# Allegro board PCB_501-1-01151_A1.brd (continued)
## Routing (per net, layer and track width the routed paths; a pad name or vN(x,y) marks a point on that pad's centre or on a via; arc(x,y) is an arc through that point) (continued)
DRAM_SDQS1_P: length 30.1
  TOP w0.102: v1(83.74,51.44) 83.74,51 83.95,50.8 83.95,48.77 82.3,47.12 82.3,45.1 82.99,44.41 U7.C7 ; v1(76.53,51.82) 76.53,51.56 76.33,51.36 76.33,51.09 76.15,50.91 76.15,50.7 76.04,50.59 75.83,50.59 75.72,50.47 75.72,50.26 75.6,50.15 75.39,50.15 75.28,50.04 75.28,49.83 75.17,49.72 74.96,49.72 74.85,49.61 74.85,49.4 74.74,49.29 74.53,49.29 73.37,48.13 72.6,48.13 72.47,48 72.2,48 72.06,48.13 69.56,48.13 69.45,48.02 69.15,48.02 69.04,48.13 68.77,48.13 68.1,47.46 66.67,47.46 U6.T1
  BOTTOM w0.102: v1(83.74,51.44) 83.95,51.23 83.95,51.03 83.85,50.92 78.57,50.92 78.47,50.83 76.45,50.83 76.33,50.95 76.33,51.61 v1(76.53,51.82)
DRAM_SDWE#: length 34.9
  TOP w0.142: U6.J1 67.4,41.78 67.75,41.43 68.3,41.43 68.69,41.83 70.24,41.83 70.38,41.69 70.38,41.41 70.52,41.27 71.3,41.27 71.44,41.13 71.44,40.79 71.3,40.65 71,40.65 70.91,40.56 70.91,40.25 71,40.16 v1(71.36,40.16) ; v1(79.41,37.61) 80.1,37.61 80.23,37.74 80.23,38.25 80.65,38.66 80.65,39.42 81.36,40.12 81.36,41.66 80.65,42.37 80.65,43.03 81.06,43.44 81.26,43.44 81.59,43.1 81.82,43.1 82.08,43.37 82.08,43.58 81.59,44.08 81.16,44.08 80.28,43.19 80.28,42.17 80.98,41.46 80.98,40.25 80.28,39.55 80.28,38.73 79.81,38.25 U7.L3
  BOTTOM w0.142: v1(71.36,40.16) 71.36,40.52 71.5,40.66 71.7,40.66 71.95,40.41 71.95,39.98 72.06,39.88 73.75,39.88 73.97,39.65 74.37,39.65 74.56,39.85 74.75,39.85 76.59,38.01 77.47,38.01 77.87,37.61 v1(79.41,37.61)
DRAM_VREF: length 41.8
  TOP w0.254: U7.M8 v1(84.21,36.81) ; U7.H1 v1(77.81,40.8) ; U6.P4 v1(64.61,46.2)
  L4_SIG2 w0.508: v1(72.39,46.35) 71.64,45.61 69.96,45.61 69.37,46.2 v1(64.61,46.2)
  BOTTOM w0.142: v1(77.81,40.8) 78.21,41.21 ; 78.21,41.21 78.21,41.77 78.44,42.01 79.79,42.01 79.82,41.97 ; 78.21,41.21 79.05,41.21 79.12,41.27
  BOTTOM w0.381: R66.1 R68.2 67.06,50.06 C88.1 67.08,49.43 66.16,48.51 65.15,48.51 64.75,48.11 C73.1 64.75,46.91 64.61,46.77 v1(64.61,46.2) ; v1(77.81,40.8) 77.36,41.26 C64.1 ; 79.12,41.27 80.14,42.29 80.9,42.29 82.8,40.39 82.8,37.97 83.19,37.59 C63.1 84.31,36.91 v1(84.21,36.81)
  BOTTOM w0.508: v1(72.39,46.35) 72.95,46.92 75.1,46.92 76.14,45.87 76.14,41.84 76.73,41.26 C64.1
DRAM_ZQPAD: length 2.6
  TOP w0.142: U6.N4 v1(64.61,45.4)
  BOTTOM w0.142: 65.75,45 65.24,45 64.84,45.4 v1(64.61,45.4)
  BOTTOM w0.381: 65.75,45 66.35,45 R65.1
ED_EN_A: length 3.5
  BOTTOM w0.142: U10.9 46.22,11.27 R798.1
ED_EN_B: length 3.9
  BOTTOM w0.142: R799.1 46.25,28.82 46.72,28.35 U10.53
EEPR_SCL: length 5.3
  BOTTOM w0.142: R136.2 80.01,61.47 82.17,63.63 83.01,63.63 83.19,63.45 U13.6
EEPR_SDA: length 3.1
  BOTTOM w0.142: U13.5 81.97,62.92 81.15,62.1 R139.2
ENET1_TXD0: length 40.7
  TOP w0.142: U6.E15 v1(54.98,38.17)
  L3_SIG1 w0.142: v1(54.98,38.17) 55.38,38.57 56.75,38.57 56.98,38.34 56.98,33.36 52.95,29.33 52.95,26.14 51.58,24.77 51.58,21.18 50.23,19.83 50.23,14.48 50.67,14.04 50.67,11.94 47.61,8.87 v1(44.56,8.87)
  BOTTOM w0.142: R78.2 v1(44.56,8.87)
ENET1_TXD1: length 46.1
  TOP w0.142: U6.E14 v1(55.78,38.17)
  L3_SIG1 w0.142: v1(42.55,10.03) 43.11,9.47 47.7,9.47 49.4,11.18 49.4,14.88 49.54,15.01 49.54,20.12 49.93,20.51 49.93,21.85 49.5,22.28 49.5,27.46 49.15,27.81 47.71,27.81 47.12,28.41 47.12,32.56 46.83,32.85 46.83,34.16 47.57,34.9 51.25,34.9 51.4,35.06 52.59,35.06 53.23,35.7 53.87,35.7 54.33,36.17 55.15,36.17 55.39,36.41 55.39,37.77 v1(55.78,38.17)
  BOTTOM w0.142: v1(42.55,10.03) 42.8,10.29 R79.2
ENET1_TXEN: length 42.8
  TOP w0.142: U6.F15 v1(54.98,38.97)
  L3_SIG1 w0.142: v1(44.12,10.09) 44.12,15.03 45.1,16.02 46.01,16.02 47.15,17.16 47.15,20.33 46.24,21.24 46.24,22.21 45.76,22.7 45.76,25.07 45.09,25.74 45.09,27.42 44.2,28.3 44.2,31.22 44.89,31.91 44.89,34.09 47.15,36.36 47.15,36.52 47.48,36.85 47.82,36.85 48.35,36.32 48.65,36.32 48.77,36.45 48.77,36.95 48.9,37.07 49.07,37.07 49.2,36.95 49.2,36.45 49.32,36.32 50.55,36.32 52,37.77 53.55,37.77 53.78,38 53.78,38.33 54.02,38.57 54.59,38.57 v1(54.98,38.97)
  BOTTOM w0.142: v1(44.12,10.09) 44.07,10.13 44.07,10.16 43.94,10.29 R80.2
ENET2_TXD0: length 13.7
  TOP w0.142: v1(53.47,33.15) 53.47,33.45 U6.A15
  L3_SIG1 w0.142: v1(53.47,33.15) 52.93,33.69 50.53,33.69 50.18,34.04 48.4,34.04 48.37,34.07 v1(47.91,34.07)
  BOTTOM w0.142: R83.2 44.43,34.16 47.3,34.16 47.4,34.07 v1(47.91,34.07)
ENET2_TXD1: length 16.7
  TOP w0.142: U6.A16 52.96,33.74 52.96,32.85 v1(53.31,32.51)
  L3_SIG1 w0.142: v1(49.43,33.53) 50.2,33.53 50.39,33.34 52.47,33.34 v1(53.31,32.51)
  BOTTOM w0.142: R84.2 42.77,33.64 42.77,34.51 43.12,34.86 46.56,34.86 46.8,34.63 48.33,34.63 v1(49.43,33.53)
ENET2_TXEN: length 12.7
  TOP w0.142: U6.B15 v1(54.98,35.77)
  L3_SIG1 w0.142: v1(54.98,35.77) 53.25,34.03 50.68,34.03 50.17,34.54 47.71,34.54 47.31,34.14 v1(47.31,33.46)
  BOTTOM w0.142: v1(47.31,33.46) 46.86,33.46 46.68,33.29 R85.2
ENET_INT_A: length 3.5
  BOTTOM w0.142: U10.18 41.72,12.25 41.66,12.19 R861.1 R863.2
ENET_INT_B: length 11.1
  TOP w0.142: R862.1 42.46,33.53 42.23,33.76 v1(42.23,34.21)
  BOTTOM w0.142: v1(42.23,34.21) 41.91,33.89 41.91,33.86 41.88,33.83 41.88,32.61 41.77,32.49 R864.2 41.27,30.15 42.22,29.21 U10.44
ENET_REF_CLK: length 35.4
  TOP w0.142: U6.D17 53.23,37.21 v1(52.39,37.21) ; U6.F14 v1(55.78,38.97)
  L3_SIG1 w0.142: v1(51.04,21.59) 51.04,24.94 52.07,25.97 52.07,28.14 51.18,29.02 49.28,29.02 47.91,30.4 v1(47.91,30.85)
  BOTTOM w0.142: v1(55.78,38.97) 55.38,39.37 52.58,39.37 52.18,38.97 R779.2 50.85,38.97 50.37,38.49 ; 50.37,38.49 50.86,37.99 R773.2 51.99,37.99 52.42,38.42 52.69,38.42 52.83,38.27 52.83,37.65 v1(52.39,37.21) ; 50.37,38.49 49.83,38.49 49.44,38.09 49.44,35.61 49.95,35.09 49.95,32.9 v1(47.91,30.85) ; U10.68 51.41,21.95 51.05,21.59 v1(51.04,21.59)
ENETPHY_RESET#: length 46.2
  TOP w0.142: U6.L17 53.17,43.38 53.01,43.22 49.77,43.22 47.46,40.9 47.46,39.82 46.03,38.39 45.62,38.39 45.62,38.38 43.46,38.38 42.55,37.47 41.88,37.47 41.12,38.23 TP48.1 40.39,37.08 v1(40.11,36.81) ; R127.2 48.13,18.92 v1(48.26,19.05)
  L4_SIG2 w0.142: v1(40.11,36.81) 39.62,36.32 39.62,27.67 44.11,23.18 44.11,21.68 46.74,19.05 v1(48.26,19.05)
  BOTTOM w0.142: v1(48.26,19.05) 48.77,19.05 50.17,20.45 U10.71
EXT_EN: length 19.9
  L3_SIG1 w0.142: v1(49.91,12.78) 49.91,14.31 49.89,14.34 49.89,19.98 50.27,20.37 50.27,21.99 49.97,22.3 49.97,25.09 50.67,25.79 50.67,27.5 49.8,28.37 v1(48.41,28.37)
  BOTTOM w0.142: R571.2 50.16,12.57 49.96,12.78 v1(49.91,12.78) ; v1(48.41,28.37) 48.39,28.34 48.22,28.17 U10.56
FB_DCDC6: length 11.7
  TOP w0.142: U1.22 42.67,62.76 42.02,63.41 42.02,69.49 41,70.5 R14.1 R13.1
FT230_CTS#: length 2.8
  BOTTOM w0.142: R174.2 19.48,44.13 U20.6
FT230_RTS#: length 7.7
  TOP w0.142: TP7.1 18.67,51.82 v1(18.67,51.31)
  BOTTOM w0.142: v1(18.67,51.31) 19.06,50.92 19.06,47.21 18.53,46.67 U20.2
GANG_EN: length 2
  TOP w0.142: R154.1 67.49,63.45 U14.34
GATE_PMOS: length 31.1
  TOP w0.142: v1(62.59,8.81) 62.76,8.64 D12.2 ; Q5.1 64.73,7.41 64.63,7.51 R193.2 63.52,7.87 D12.2 ; D12.2 62.76,7.29 62.32,6.86 R192.2 61.36,5.86 61.16,5.66 Q4.1 ; Q6.1 82.6,5.92 82.64,5.97 R262.2 83.29,6.33 83.57,6.6 v1(83.57,6.62)
  L4_SIG2 w0.142: v1(83.57,6.62) 83.11,6.62 82.97,6.48 67.08,6.48 64.38,9.17 62.95,9.17 v1(62.59,8.81)
GPANIO: length 0.6
  TOP w0.142: U6.R13 v1(56.58,47)
GPIO1_IO22: length 2.2
  TOP w0.142: H4.2 14.31,51.75 R841.1
GPIO1_IO24: length 43.9
  TOP w0.142: U6.H17 52.96,40.98 49.28,37.3 49.28,36.81 46.63,34.16 43.89,34.16 43.74,34.31 v1(43.29,34.31)
  L3_SIG1 w0.142: v1(43.29,34.31) 42.22,33.24 42.08,33.24 40.17,31.33 40.17,26.04 40.36,25.85 40.36,25.22 42.51,23.06 42.51,22.51 44.58,20.45 44.58,18.7 41.52,15.64 v1(41.52,9.75)
  BOTTOM w0.142: v1(41.52,9.75) 41.52,10.2 41.66,10.34 R861.2
GPIO1_IO25: length 12.4
  TOP w0.142: R862.2 46.64,33.53 49.77,36.67 49.77,37.24 52.17,39.64 52.17,39.7 53.1,40.63 54.25,40.63 U6.H16
GPIO3_IO03: length 65.6
  TOP w0.142: v1(60.58,36.58) 60.2,36.96 U6.C9 ; H4.20 14.31,38.31 v1(13.97,37.97)
  L3_SIG1 w0.142: v1(60.58,36.58) 60.58,29.34 v1(59.56,28.32)
  L4_SIG2 w0.142: v1(41.91,34.79) 48.85,34.79 50.24,33.4 51.31,33.4 51.59,33.12 51.59,32.19 53.34,30.44 53.34,27.69 53.85,27.18 56.13,27.18 57.28,28.32 v1(59.56,28.32)
  BOTTOM w0.142: v1(41.91,34.79) 38.34,34.79 37.34,33.78 35.43,33.78 33.75,32.1 32.99,32.1 32.51,31.62 28.07,31.62 21.72,37.97 v1(13.97,37.97)
GPIO5_IO02: length 2.6
  TOP w0.142: H4.4 R834.2
GPIO5_IO03: length 2.6
  TOP w0.142: H4.6 R835.2
GPIO5_IO04: length 68
  TOP w0.142: U6.P9 v1(59.78,46.2) ; H4.8 v1(16.13,46.48)
  L3_SIG1 w0.142: v1(59.78,46.2) 59.38,46.6 59.38,47.16 59.15,47.39 59.15,50.64 v1(63.25,54.74)
  L4_SIG2 w0.142: v1(16.13,46.48) 16.93,45.68 25.64,45.68 31.14,51.18 34.42,51.18 35.18,50.42 41.4,50.42 42.31,51.33 48.6,51.33 51.3,54.02 56.62,54.02 59.03,51.61 59.03,49.94 59.82,49.15 59.82,46.68 59.78,46.65 v1(59.78,46.2)
  BOTTOM w0.142: v1(63.25,54.74) 63.14,54.84 R866.2
GPIO5_IO05: length 66.3
  TOP w0.142: H4.10 12.32,45.21 12.08,45.45 R867.2 12.97,47.12 15.75,47.12 16,47.37 v1(16,47.37) ; U6.N8 v1(60.58,45.4)
  L4_SIG2 w0.142: v1(16,47.37) 17.35,46.02 24.43,46.02 25.77,47.36 26.35,47.36 31,52.02 48.32,52.02 51.73,55.43 57.6,55.43 61.68,51.35 61.68,50.08 61.68,50.08 61.68,49.69 61.68,49.68 61.68,48.42 60.99,47.73 60.99,45.8 v1(60.58,45.4)
GPIO5_IO06: length 63.6
  TOP w0.142: v1(10.71,44.17) 10.71,43.67 11.2,43.18 11.94,43.18 12.21,43.45 R868.2 H4.12 ; U6.N11 v1(58.18,45.4)
  L3_SIG1 w0.142: v1(36.68,48.22) 35.88,49.02 28.32,49.02 27.08,47.78 23.42,47.78 23.33,47.88 22.82,47.88 22.31,48.39 19.05,48.39 16.51,45.85 12.43,45.85 11.08,44.5 11.03,44.5 v1(10.71,44.17)
  L4_SIG2 w0.142: v1(36.68,48.22) 37.13,48.22 37.32,48.42 42.19,48.42 43.94,50.16 48.91,50.16 51.45,52.7 54.99,52.7 57.91,49.78 57.91,49.35 58.15,49.35 58.58,48.92 58.58,45.79 v1(58.18,45.4)
GPIO5_IO07: length 58.5
  TOP w0.142: U6.N10 v1(58.98,45.4) ; H4.14 15.87,42.67 16.53,43.32 20.26,43.32 21.01,44.07 23.11,44.07 v1(23.75,44.7) R869.2
  L4_SIG2 w0.142: v1(58.98,45.4) 59.38,45.79 59.38,49.09 58.64,49.84 58.64,51.45 56.41,53.68 51.44,53.68 48.75,50.98 42.73,50.98 41.78,50.04 34.54,50.04 33.79,50.79 31.24,50.79 25.16,44.7 v1(23.75,44.7)
GPIO5_IO08: length 93.1
  TOP w0.142: v1(25.91,46.74) 25.91,45.97 24.6,44.67 24.6,40.1 21.86,37.36 16.16,37.36 16.05,37.47 13.78,37.47 13,38.24 13,38.24 12.85,38.39 12.85,38.39 12.45,38.8 12.45,40.38 13.47,41.4 H4.16 ; R870.2 v1(72.36,56.77) ; U6.N9 v1(59.78,45.4)
  L3_SIG1 w0.142: v1(72.36,56.77) 69.79,54.2 63.26,54.2 59.5,50.43 59.5,47.43 59.65,47.27 59.65,46.89 60.18,46.36 60.18,46.03 60.1,45.95 60.1,45.72 v1(59.78,45.4)
  L4_SIG2 w0.142: v1(59.78,45.4) 60.18,45.79 60.18,49.29 59.72,49.75 59.72,52.73 57.36,55.09 51.87,55.09 48.46,51.67 31.15,51.67 26.21,46.74 v1(25.91,46.74)
GPIO5_IO09: length 78.2
  TOP w0.142: v1(24.77,47.12) 24.77,45.59 24.26,45.09 24.26,40.37 21.94,38.05 16.45,38.05 15.76,38.73 15.76,39.51 15.14,40.13 H4.18 ; U6.R6 v1(62.21,46.2)
  L4_SIG2 w0.142: v1(62.21,46.2) 61.81,46.6 61.81,47.16 62.06,47.41 62.06,51.56 57.49,56.13 53.85,56.13 53.49,55.78 51.59,55.78 48.17,52.36 30.86,52.36 26.39,47.89 25.54,47.89 v1(24.77,47.12)
  BOTTOM w0.142: R871.2 65.28,53.01 64.17,51.89 64.17,50.81 64.95,50.03 64.95,48.97 64.3,48.32 63.77,48.32 63.38,47.93 63.38,46.83 63.15,46.6 62.61,46.6 v1(62.21,46.2)
HUB_CFG_SEL1: length 6.8
  TOP w0.142: R142.2 R146.1 71.25,59.95 71.37,60.06 71.37,63.83 71.49,63.96 U14.42
HUB_CFG_SEL2: length 2.5
  TOP w0.142: v1(68.33,74.55) 68.45,74.42 68.45,73.75 U14.13
  BOTTOM w0.142: R147.1 68.58,74.29 v1(68.33,74.55) R143.2
HUB_LEDA1#: length 7.4
  TOP w0.203: DA1.3 88.98,97.93 88.97,97.92 88.65,97.92 88.01,97.28 88.01,95.63 88.63,95.02 R150.2 90.17,95.99 90.14,96.02 DA1.2
HUB_LEDA2#: length 6.8
  TOP w0.203: DA2.3 69.99,97.93 69.09,97.03 69.09,95.88 69.72,95.25 70.71,95.25 70.73,95.27 R151.2 71.25,95.79 71.22,95.82 DA2.2
HUB_LEDA3#: length 7.1
  TOP w0.203: DA3.2 67.79,96.02 67.82,95.99 R153.2 67.3,95.27 67.19,95.38 66.17,95.38 65.66,95.88 65.66,97.66 65.93,97.93 DA3.3
HUB_LEDA4#: length 7.6
  TOP w0.203: DA4.2 48.74,95.69 48.77,95.66 R157.2 47.1,95.14 46.48,95.76 46.48,97.66 46.75,97.93 DA4.3
HUB_LEDA5#: length 7
  TOP w0.203: DA5.2 36.04,95.89 35.94,95.79 R158.2 34.27,95.27 33.91,95.63 33.91,97.41 34.42,97.92 34.86,97.92 34.88,97.93 DA5.3
HUB_OCS1#: length 5
  TOP w0.142: R155.2 C161.1 64.42,65.29 64.42,65.55 64.67,65.8 64.67,66.46 65.8,67.59 U14.28
HUB_OCS2#: length 3.7
  TOP w0.142: U14.27 65.8,68.09 65.02,67.31 C162.1 R156.2
HUB_OCS3#: length 3.6
  TOP w0.142: U14.22 65.8,70.59 65.37,71.03 64.83,71.03 R159.2 C163.1
HUB_OCS4#: length 3.5
  TOP w0.142: R160.2 C164.1 65.27,71.63 65.8,71.09 U14.21
HUB_OCS5#: length 25.7
  TOP w0.142: v1(66.17,60.32) 67.18,60.32 67.59,60.74 67.59,61.67 67.81,61.88 67.81,62.86 68.09,63.14 R820.1 68.33,63.63 67.99,63.96 U14.35
  L3_SIG1 w0.142: v1(58.89,73.09) 59.67,73.09 59.83,73.25 61.88,73.25 64.52,70.61 64.52,66.8 65.85,65.47 65.85,60.64 v1(66.17,60.32)
  BOTTOM w0.142: U19.2 58.37,73.03 58.44,73.09 v1(58.89,73.09)
HUB_PWR_EN1: length 43.2
  TOP w0.142: v1(85.6,62.48) 85.6,59.18 82.36,55.95 69.4,55.95 65.37,59.97 65.37,62.94 64.77,63.54 64.77,65.41 65.02,65.65 65.02,66.3 65.8,67.09 U14.29
  BOTTOM w0.142: U18.3 92.33,61.16 91.01,62.48 v1(85.6,62.48)
HUB_PWR_EN2: length 50
  TOP w0.142: U14.26 65.84,68.59 65.7,68.45 65.66,68.45 65.28,68.07 61.47,68.07 61.09,67.69 61.09,65.15 62.49,63.75 62.49,61.1 68.68,54.91 83.36,54.91 87.38,58.93 v1(87.38,61.98)
  BOTTOM w0.142: v1(87.38,61.98) 90.25,61.98 91.06,61.16 U18.4
HUB_PWR_EN3: length 46
  TOP w0.142: U14.23 65.73,70.09 65.72,70.1 65.32,70.1 64.9,69.67 64.9,68.83 64.48,68.42 61.32,68.42 60.74,67.83 60.74,65.01 62.15,63.6 62.15,60.95 68.54,54.56 84.03,54.56 v1(87,57.53)
  BOTTOM w0.142: U18.7 87.25,58.24 87,57.98 v1(87,57.53)
HUB_PWR_EN4: length 56.2
  TOP w0.142: v1(87.38,56.39) 87.38,55.63 85.28,53.53 67.98,53.53 61.11,60.4 61.11,63.17 59.6,64.68 59.6,70.63 60.32,71.35 60.32,72.97 60.89,73.53 64.4,73.53 65.02,72.91 65.02,72.37 65.8,71.59 U14.20
  BOTTOM w0.142: v1(87.38,56.39) 87,56.77 86.61,56.77 85.98,57.4 U18.8
HUB_PWR_EN5: length 22.9
  TOP w0.142: v1(65.28,64.01) 65.28,65.43 65.36,65.51 65.36,66.15 65.8,66.59 U14.30
  L4_SIG2 w0.142: v1(58.17,65.02) 58.64,65.5 63.78,65.5 v1(65.28,64.01)
  BOTTOM w0.142: v1(58.17,65.02) 59.15,66.01 59.15,70.18 59.56,70.59 59.56,73.41 58.67,74.29 U19.1
HUB_RESET#: length 202.2
  TOP w0.142: v1(71.52,57.26) 71.84,57.58 71.84,60.28 72.52,60.96 72.52,62.99 72.37,63.14 R144.1 71.88,63.85 71.99,63.96 U14.43 ; U6.N17 53.32,44.98 52.97,45.33 52.06,45.33 51.56,44.83 48.9,44.83 47.24,43.18 47.24,42.42 45.97,41.15 TP60.1 41.02,41.15 37.72,37.85 v1(32.7,37.85)
  L4_SIG2 w0.142: v1(32.7,37.85) 32.27,37.41 32.27,32.01 30.76,30.51 30.76,16.57 34.98,12.35 48.18,12.35 48.97,11.56 48.97,8.53 55.43,2.08 84.88,2.08 96.9,14.1 96.9,21.8 97.12,22.02 97.12,26.37 97.04,26.45 97.04,26.85 97.12,26.93 97.12,34.49 97.32,34.69 97.32,49.36 95.88,50.8 95.88,54.23 94.42,55.7 88.81,55.7 87.61,56.9 84.84,56.9 83.57,55.63 78.87,55.63 77.34,57.15 75.44,57.15 75.23,57.36 72.18,57.36 72.08,57.26 v1(71.52,57.26)
HUB_VDDA18PLL: length 2.7
  TOP w0.254: U14.62 v1(75.9,72.09)
  BOTTOM w0.381: v1(75.9,72.09) 75.86,72.14 C132.1 C134.1
HUB_VDDDIG18: length 2.8
  TOP w0.254: U14.25 65.66,69.09 v1(65.53,68.96)
  BOTTOM w0.381: C135.1 C136.1 v1(65.53,68.96)
I2C2_CURSENSE_SCL: length 130
  TOP w0.142: v1(37,35.64) 35.98,35.64 34.73,36.9 32.58,36.9 31.15,35.46 28.63,35.46 28.35,35.74 28.35,35.76 26.25,37.86 26.25,43.55 30.05,47.35 31.87,47.35 32.42,46.8 33.17,46.8 33.24,46.86 v1(33.69,46.86) 34.01,47.18 34.01,47.89 32.97,48.93 29.91,48.93 27.46,51.37 v1(24.32,51.37) ; U6.F17 53.4,38.99 v1(53.4,38.97)
  L3_SIG1 w0.142: v1(37,35.64) 37.85,34.8 41.19,34.8 41.83,35.43 43.69,35.43 45.22,36.96 45.22,37.45 46.75,38.97 v1(53.4,38.97) ; v1(24.32,51.37) 24,51.69 19.56,51.69 19.53,51.72 19.47,51.72 18.4,52.8 10.2,52.8 8.51,54.48 8.51,72.77 10.8,75.06 15.62,75.06 17.2,76.64 30.66,76.64 31.02,76.28 31.04,76.28 31.32,76 31.32,75.98 31.62,75.67 v1(31.62,73.41)
  BOTTOM w0.142: U22.6 33.58,46.3 33.69,46.41 v1(33.69,46.86) ; v1(31.62,73.41) 33.02,73.41 33.91,72.52 34.35,72.52 34.6,72.26 U23.6 ; v1(24.32,51.37) 25.21,51.37 25.27,51.44 R181.2
I2C2_CURSENSE_SDA: length 139.9
  TOP w0.142: v1(35.98,34.98) 35.66,35.3 35.59,35.3 34.34,36.55 32.74,36.55 31.39,35.2 31.37,35.2 31.29,35.12 28.49,35.12 28.01,35.6 28.01,35.62 25.91,37.72 25.91,43.7 30.02,47.81 31.91,47.81 32.56,47.15 32.96,47.15 33.02,47.21 33.09,47.21 v1(33.41,47.53) 33.41,47.99 32.82,48.58 29.76,48.58 27.5,50.84 24.01,50.84 v1(23.69,51.16) ; U6.G13 v1(56.58,39.77)
  L3_SIG1 w0.142: v1(35.98,34.98) 35.98,35.6 36.58,36.2 37.47,36.2 38.52,35.14 40.1,35.14 40.89,35.94 43.58,35.94 44.87,37.23 44.87,37.59 47.29,40.01 51.15,40.01 51.79,39.37 56.19,39.37 v1(56.58,39.77) ; v1(23.69,51.16) 19.49,51.16 18.2,52.45 10.05,52.45 8.16,54.34 8.16,72.91 10.68,75.43 15.36,75.43 16.91,76.98 31.47,76.98 32.26,76.2 v1(32.26,73.91)
  BOTTOM w0.142: U22.7 33.89,45.65 34.17,45.92 34.17,47.23 33.87,47.53 v1(33.41,47.53) ; R182.2 25.82,49.91 25.47,50.26 24.59,50.26 v1(23.69,51.16) ; U23.7 35.25,72.39 34.74,72.9 34.04,72.9 33.02,73.91 v1(32.26,73.91)
I2C4_HUB_EEPR_SCL: length 207.6
  TOP w0.142: R89.1 40.61,35.94 39.97,35.31 TP59.1 39.76,34.79 39.76,33.48 38.79,32.51 34.91,32.51 34.87,32.48 31.1,32.48 30.94,32.64 v1(30.49,32.64) ; U14.41 70.99,63.96 70.61,63.58 R137.2 70.38,63.14 69.98,62.75 69.98,61.48 69.96,61.45 R145.1 69.34,60.34 69.34,58.04 70.49,56.9 v1(70.61,56.9)
  L4_SIG2 w0.142: v1(70.61,56.9) 70.61,58.05 71.11,58.55 76.58,58.55 79.16,55.97 83.15,55.97 85.22,58.04 87.16,58.04 87.47,57.73 87.47,57.52 88.95,56.04 94.56,56.04 96.27,54.34 96.27,50.91 98.27,48.9 98.27,14.96 85.04,1.73 55.12,1.73 48.49,8.36 48.49,10.44 47.62,11.3 44.56,11.3 44.09,11.78 35.07,11.78 30.42,16.42 30.42,31.18 30.49,31.25 v1(30.49,32.64)
  BOTTOM w0.142: R136.1 79.23,60.05 78.1,58.93 78.1,56.64 77.5,56.04 71.47,56.04 v1(70.61,56.9)
I2C4_HUB_EEPR_SDA: length 210.3
  TOP w0.142: v1(29.64,32.61) 30.11,32.13 31.87,32.13 31.88,32.12 32.28,32.12 32.29,32.13 38.9,32.13 40.11,33.34 40.11,33.75 41.63,35.27 42.11,35.27 42.19,35.18 TP58.1 43.66,35.18 44.04,34.8 R90.1 ; v1(69.5,57.05) 69.5,57.12 68.83,57.79 68.83,60.83 68.96,60.96 68.96,61.96 68.95,61.97 68.95,62.73 69.36,63.14 R138.2 69.47,63.75 69.85,64.13 70.24,64.13 70.49,64.39 U14.40
  L4_SIG2 w0.142: v1(29.64,32.61) 30.07,32.17 30.07,16.01 34.65,11.43 43.94,11.43 44.58,10.8 45.09,10.8 45.33,10.55 45.33,10.55 54.5,1.38 85.18,1.38 98.62,14.82 98.62,49.04 96.61,51.05 96.61,54.48 94.71,56.39 91.15,56.39 89.5,58.03 89.5,58.45 88.8,59.15 85.69,59.15 84.96,58.42 81.77,58.42 81.26,58.93 70.35,58.93 69.4,57.98 69.4,57.22 69.5,57.12 v1(69.5,57.05)
  BOTTOM w0.142: v1(69.5,57.05) 69.57,57.05 70.93,55.69 77.64,55.69 78.45,56.5 78.45,58.62 79.14,59.31 80.41,59.31 R139.1
I2C4_SCL: length 11.1
  TOP w0.142: U6.J17 51.44,41.78 49.15,39.5 49.15,38.61 46.48,35.94 R89.2
I2C4_SDATA: length 12.9
  TOP w0.142: U6.J16 54.22,41.4 51.56,41.4 49.49,39.33 49.49,38 48.9,37.41 48.9,36.92 46.78,34.8 R90.2
I.MX_ONOFF: length 63.8
  TOP w0.142: v1(60.59,46.22) 60.95,46.58 U6.R8 ; SW3.2 97.21,77.39 97.16,77.34 C598.1 96.67,76.85 91.44,71.63 91.44,61.47 89.66,59.69 89.66,56.64 86.2,53.18 75.11,53.18 75.11,53.18 73.63,53.18 v1(73.28,52.83)
  L3_SIG1 w0.142: v1(73.28,52.83) 72.39,53.72 63.31,53.72 60.95,51.36 60.93,51.36 59.84,50.27 59.84,47.46 60.59,46.72 v1(60.59,46.22)
INT_LDO: length 3.2
  TOP w0.142: C34.1 39.24,55.88 40.49,57.13 U1.35
IOVDD_LCD: length 51.7
  TOP w0.254: Q5.3 65.73,7.77 65.27,8.23 64.18,8.23 v1(63.75,8.66)
  TOP w0.381: C183.1 66.53,4.97 v1(67.72,3.78) 67.72,3.21 68.38,2.55 74.43,2.55 78.49,6.6 79.7,6.6 80.59,7.49 80.59,9.78 81.41,10.6 v1(81.41,11.18) ; C183.1 65.91,5.58 66.28,5.95 R191.2 ; C183.1 C187.1
  L4_SIG2 w0.381: v1(57.99,3.55) 59,2.54 66.47,2.54 v1(67.72,3.78) 67.72,4.7 v1(63.75,8.66)
  BOTTOM w0.254: J9.33 57.5,4.3 57.99,3.81 v1(57.99,3.55)
  BOTTOM w0.381: R195.1 v1(81.41,11.18) 81.41,11.75 81.79,12.13 81.79,12.85 81,13.64 R807.1
IOVDD_LCD_SW_IN: length 8
  TOP w0.142: Q5.2 65.08,6.41 65.02,6.35
  TOP w0.381: R193.1 64.24,6.35 65.86,6.35 66.26,6.75 R191.1 C186.1 FB6.2 FB8.2
JTAG_DACK: length 3.3
  TOP w0.142: H5.19 R848.2
JTAG_DE: length 3.3
  TOP w0.142: R265.1 H5.17
JTAG_MOD: length 27.1
  TOP w0.142: U6.P15 v1(54.98,46.2)
  L3_SIG1 w0.142: v1(35.1,39.66) 35.42,39.98 35.91,39.98 40.64,44.7 40.64,45.85 41.78,46.99 48.01,46.99 48.6,47.58 51.99,47.58 53.37,46.2 v1(54.98,46.2)
  BOTTOM w0.142: R387.1 R569.2 34.99,39.37 35.1,39.48 v1(35.1,39.66)
JTAG_PWR: length 3.8
  TOP w0.381: R264.2 4.3,49.02 C572.1 4.32,49.65 4.26,49.71 H5.2
JTAG_RTCK: length 3.3
  TOP w0.142: R851.2 H5.11
JTAG_SRST#: length 23.8
  TOP w0.142: R856.2 v1(14.22,54.23) ; H5.15 R266.1 12.05,68.97 12.33,68.69 D26.1 12.33,67.99 12.72,67.59 13.56,67.59 15.49,65.66 15.49,58.02 v1(16.52,56.99)
  L3_SIG1 w0.142: v1(14.22,54.23) 14.22,54.68 14.71,55.16 14.72,55.16 15.28,55.72 16.22,55.72 16.51,56.01 16.51,56.52 16.52,56.53 v1(16.52,56.99)
JTAG_TCK: length 66.7
  TOP w0.142: v1(16.3,54.36) 16.3,55.08 15.43,55.94 15.43,56.05 14.64,56.85 14.64,59.53 13.84,60.32 12.32,60.32 12.05,60.6 R852.2 H5.9 ; U6.M14 v1(55.78,44.6)
  L3_SIG1 w0.142: v1(16.3,54.36) 17.53,54.36 17.76,54.59 24.4,54.59 26.49,52.51 36.63,52.51 37.52,51.62 47.93,51.62 49.99,53.68 56.05,53.68 56.77,52.96 56.77,51.31 54.74,49.28 54.74,47.01 55.38,46.36 55.38,45 v1(55.78,44.6)
JTAG_TDI: length 58.1
  TOP w0.142: H5.5 R854.1 12.05,56.08 12.25,55.88 13.46,55.88 v1(13.9,55.44) ; v1(51.81,48.89) 52.36,48.33 52.36,46.73 53.65,45.43 53.91,45.43 54.36,44.98 U6.N16
  L3_SIG1 w0.142: v1(51.81,48.89) 52.26,49.34 52.26,52.53 51.79,53 50.22,53 48.4,51.19 47.04,51.19 46.33,51.19 46.33,51.19 37.34,51.19 37.09,51.44 36.45,52.08 25.14,52.08 24,53.21 21.84,53.21 20.96,54.1 17.91,54.1 17.53,53.72 13.84,53.72 13.46,54.1 13.46,55 v1(13.9,55.44)
JTAG_TDO: length 71.7
  TOP w0.142: H5.13 13.34,66.93 15.11,65.15 15.11,57.02 v1(15.88,56.26) ; U6.N15 54.98,45.4 54.49,45.4 54.25,45.64 54.25,45.83 53.84,46.23 53.63,46.23 52.7,47.16 52.7,48.76 52,49.46 51.9,49.46 v1(51.76,49.6)
  L3_SIG1 w0.142: v1(51.76,49.6) 51.76,50.05 51.92,50.21 51.92,52.38 51.64,52.66 50.36,52.66 48.55,50.85 47.18,50.85 47.18,50.85 46.19,50.85 37.2,50.85 36.74,51.3 36.31,51.73 24.87,51.73 23.9,52.7 19.94,52.7 19.43,53.21 13.84,53.21 12.83,54.23 12.83,55.37 13.72,56.26 v1(15.88,56.26)
JTAG_TMS: length 65
  TOP w0.142: v1(15.64,54.31) 15.64,55.13 15,55.77 15,55.88 14.21,56.67 14.21,59.36 13.74,59.82 12.33,59.82 12.05,59.54 R267.1 H5.7 ; U6.P14 v1(55.78,46.2)
  L3_SIG1 w0.142: v1(55.78,46.2) 55.78,46.34 55.01,47.12 55.01,48.9 55.16,49.06 55.16,49.1 57.2,51.13 57.2,53.14 56.23,54.1 49.66,54.1 47.6,52.04 37.96,52.04 37.05,52.96 27.07,52.96 25.01,55.02 15.89,55.02 15.64,54.77 v1(15.64,54.31)
JTAG_TRST#: length 65.6
  TOP w0.142: R856.1 H5.3 ; R856.1 R855.1 ; R856.1 12.05,54.72 12.32,54.99 13.67,54.99 13.92,54.74 14.47,54.74 v1(14.98,54.23) ; U6.N14 v1(55.78,45.4)
  L3_SIG1 w0.142: v1(55.78,45.4) 56.19,45.8 56.19,49.63 58.26,51.71 58.26,53.85 56.87,55.24 55.5,55.24 54.86,54.61 49.66,54.61 47.44,52.39 38.1,52.39 37.19,53.3 27.21,53.3 25.15,55.37 15.67,55.37 14.98,54.68 v1(14.98,54.23)
JTAG_VREF: length 3.3
  TOP w0.381: R857.1 H5.1
LCD_CS#: length 2.3
  BOTTOM w0.142: J9.31 58.5,6.54 R194.1
LCD_DATA0: length 55.8
  TOP w0.142: v1(69.47,18.29) 69.47,17.26 68.84,16.63 68.1,16.63 66.17,14.69 66.17,9.67 v1(66.78,9.06) ; v1(59.56,22.58) 59.56,22.59 59.56,23.03 58.33,24.26 58.33,29.88 60.55,32.1 60.55,35.83 U6.B9
  L3_SIG1 w0.142: v1(66.78,9.06) 65.91,8.18 62.14,8.18 v1(61.6,8.73)
  BOTTOM w0.142: R236.2 v1(61.6,8.73) 60.5,7.64 J9.27 ; v1(69.47,18.29) 69.47,20.57 69.85,20.96 69.85,22.76 69.47,23.14 SW6.1 68.57,24 68.43,23.86 68.43,22.85 66.12,20.55 64.11,20.55 63.43,21.23 63.43,21.23 62.08,22.58 v1(59.56,22.58)
LCD_DATA1: length 45.1
  TOP w0.142: R231.2 67.69,10.54 v1(67.44,10.8) ; U6.A9 60.2,34.8 60.19,34.79 60.19,32.38 57.98,30.17 57.98,24.12 59.09,23.01 59.09,21.94 60.17,20.85 60.17,13.95 58.51,12.29 58.51,11.99 59.17,11.33 v1(59.51,11.33)
  L3_SIG1 w0.142: v1(67.44,10.8) 65.79,9.14 63.6,9.14 v1(62.48,10.26) 62.48,10.71 61.76,11.43 60.07,11.43 59.96,11.33 v1(59.51,11.33)
  BOTTOM w0.142: R238.2 v1(62.48,10.26) 62.48,9.39 62.11,9.01 62.11,8.13 61,7.03 J9.26
LCD_DATA2: length 52.4
  TOP w0.142: R230.2 70.08,8.36 v1(70.61,8.89) ; U6.E10 v1(58.98,38.17)
  L3_SIG1 w0.142: v1(59.96,25.5) 59.45,25.5 59,25.04 59,21.59 62.17,18.41 64.98,18.41 65.91,17.49 65.91,14.35 64.01,12.45 v1(64.01,9.65) 65.02,9.65 66.68,11.3 68.2,11.3 v1(70.61,8.89)
  BOTTOM w0.142: J9.25 61.5,6.95 63.25,8.7 R239.2 63.73,9.38 v1(64.01,9.65) ; v1(58.98,38.17) 58.98,37.93 59.44,37.48 59.44,36.23 58.93,35.73 58.93,33.56 58.04,32.67 58.04,27.42 v1(59.96,25.5)
LCD_DATA3: length 46.1
  TOP w0.142: U6.D10 v1(58.98,37.37) ; R229.2 68.58,13.34 v1(68.83,13.08)
  L3_SIG1 w0.142: v1(59.82,24.51) 60.14,24.19 60.14,21.67 62.41,19.4 65.35,19.4 66.29,18.46 66.29,14.84 67.67,13.46 68.45,13.46 v1(68.83,13.08)
  BOTTOM w0.142: J9.24 62,6.23 64.49,8.72 64.49,10.07 66.99,12.57 68.33,12.57 v1(68.83,13.08) 68.83,13.7 R240.2 ; v1(59.82,24.51) 59.36,24.51 58.17,25.71 58.17,26.31 57.35,27.13 57.35,32.94 58.17,33.75 58.17,35.94 58.59,36.36 58.59,36.97 v1(58.98,37.37)
LCD_DATA4: length 46.9
  TOP w0.142: R228.1 69.34,11.3 69.6,11.56 v1(69.6,11.78) ; U6.C10 v1(58.98,36.57)
  L3_SIG1 w0.142: v1(69.6,11.78) 69.6,12.99 68.62,13.97 67.65,13.97 66.68,14.95 66.68,18.56 65.49,19.75 62.55,19.75 60.83,21.46 v1(60.83,24.64)
  BOTTOM w0.142: R241.2 v1(69.6,11.78) 68.92,11.78 68.74,11.96 66.87,11.96 64.83,9.93 64.83,9.35 64.83,8.57 62.5,6.24 J9.23 ; v1(60.83,24.64) 60.45,25.02 59.56,25.02 58.51,26.07 58.51,26.46 57.69,27.27 57.69,32.8 58.51,33.62 58.51,35.91 58.98,36.38 v1(58.98,36.57)
LCD_DATA5: length 58.9
  TOP w0.142: U6.B10 59.05,35.83 59.05,34.01 56.9,31.86 56.9,23.01 57.81,22.1 v1(58.26,22.1) ; v1(70.36,13.08) 70.36,14.1 69.85,14.6 69.85,16.26 70.74,17.14 v1(70.74,19.18)
  BOTTOM w0.142: v1(70.74,19.18) SW6.2 70.74,24.89 70.49,25.15 68.95,25.15 68,24.19 68,22.91 65.98,20.89 64.25,20.89 63.57,21.57 62.09,23.06 59.22,23.06 v1(58.26,22.1) ; J9.22 63,6.26 65.18,8.43 65.18,9.49 65.18,9.79 67.01,11.62 68.5,11.62 68.81,11.3 69.4,11.3 69.4,11.3 69.79,11.3 69.8,11.3 70.1,11.3 70.36,11.56 v1(70.36,13.08) 70.36,13.8 R242.2
LCD_DATA6: length 58.5
  TOP w0.142: v1(72.01,19.18) 71.4,18.57 71.4,15.07 71.6,14.88 71.6,13.65 71.12,13.17 v1(71.12,11.56) ; U6.A10 59.4,33.87 57.28,31.75 57.28,23.62 v1(58.04,22.86)
  BOTTOM w0.142: J9.21 63.5,6.27 65.52,8.29 65.52,9.64 67.15,11.27 68.36,11.27 68.71,10.92 70.49,10.92 v1(71.12,11.56) R243.2 ; v1(58.04,22.86) 58.58,23.4 62.23,23.4 63.71,21.92 64.4,21.24 65.82,21.24 67.65,23.07 67.65,24.33 68.84,25.52 71.76,25.52 72.01,25.27 SW6.3 v1(72.01,19.18)
LCD_DATA7: length 60.7
  TOP w0.142: U6.D11 v1(58.18,37.37) ; v1(71.88,13.08) 71.94,13.14 71.94,14.28 72.52,14.86 72.52,18.41 v1(73.28,19.18)
  BOTTOM w0.142: R244.2 v1(71.88,13.08) 71.88,11.56 70.87,10.54 67.86,10.54 67.63,10.32 66.83,10.32 65.87,9.35 65.87,8.14 64,6.28 J9.20 ; v1(73.28,19.18) SW6.4 73.28,24.26 73.82,24.8 73.82,25.5 73.41,25.91 68.74,25.91 67.27,24.44 67.27,23.32 66.21,22.27 64.96,22.27 64.69,21.99 64.13,21.99 63.86,22.27 63.86,22.27 62.35,23.77 59.54,23.77 57.79,25.53 57.79,26.21 57,26.99 57,33.07 57.79,33.85 57.79,36.97 v1(58.18,37.37)
LCD_DATA8: length 61.7
  TOP w0.142: R224.2 v1(72.64,11.56) ; v1(55.68,12.12) 56.21,12.64 56.21,32.14 58.17,34.1 58.17,35.75 U6.B11
  L3_SIG1 w0.142: v1(72.64,11.56) 72.64,9.29 70.76,7.4 59.15,7.4 56.26,10.29 56.26,10.7 55.8,11.17 55.8,11.25 55.68,11.37 v1(55.68,12.12)
  BOTTOM w0.142: J9.19 64.5,6.29 66.3,8.09 66.3,9.25 66.99,9.94 67.85,9.94 68.07,10.16 71.25,10.16 v1(72.64,11.56) R245.2
LCD_DATA9: length 61.6
  TOP w0.142: U6.A11 58.6,34.05 56.55,32 56.55,12.79 56.98,12.36 56.98,11.64 v1(57.3,11.32) ; R223.2 v1(73.41,13.08)
  L3_SIG1 w0.142: v1(73.41,13.08) 71.88,11.56 71.88,9.02 70.61,7.75 60.82,7.75 58.68,9.89 58.68,9.9 58.47,10.11 58.47,10.61 57.75,11.32 v1(57.3,11.32)
  BOTTOM w0.142: R223.2 v1(73.41,13.08) 73.41,11.64 71.54,9.78 68.48,9.78 65,6.3 J9.18
LCD_DATA10: length 58.7
  TOP w0.142: U6.E12 v1(57.38,38.17) ; R222.2 v1(74.29,11.56)
  L3_SIG1 w0.142: v1(74.29,11.56) 75.53,12.8 75.53,13.37 74.29,14.61 73.53,14.61 72.01,16.13 68.45,16.13 67.4,17.18 67.4,18.81 65.78,20.44 63.89,20.44 63.12,21.21 61.85,21.21 61.34,21.72 61.34,25.02 60.32,26.03 58.67,26.03 57.53,27.18 54.99,27.18 54.48,27.69 54.48,28.48 v1(54.94,28.93)
  BOTTOM w0.142: R247.2 v1(74.29,11.56) 72.14,9.4 68.59,9.4 65.5,6.31 J9.17 ; v1(54.94,28.93) 55.38,29.38 55.38,36.75 55.6,36.97 55.95,36.97 56.18,37.2 56.18,37.53 56.42,37.77 56.98,37.77 v1(57.38,38.17)
LCD_DATA11: length 56.2
  TOP w0.142: U6.D12 v1(57.38,37.37) ; R221.2 v1(75.06,13.08)
  L3_SIG1 w0.142: v1(62.74,20.7) 63.35,20.09 65.64,20.09 67.06,18.67 67.06,15.11 67.69,14.48 72.77,14.48 74.17,13.08 v1(75.06,13.08)
  BOTTOM w0.142: v1(57.38,37.37) 56.99,36.97 56.99,34.07 56.31,33.4 56.31,26.36 57.07,25.61 57.07,22.13 57.92,21.28 59.12,21.28 59.47,21.63 61.81,21.63 v1(62.74,20.7) ; J9.16 66,6.31 68.07,8.38 71.88,8.38 75.06,11.56 v1(75.06,13.08) R221.2
LCD_DATA12: length 55.7
  TOP w0.142: R220.2 v1(75.82,11.56) ; U6.C12 v1(57.38,36.57)
  L3_SIG1 w0.142: v1(67.93,18.73) 68.25,18.41 68.26,18.41 69.02,17.65 73.53,17.65 76.33,14.86 76.33,13.5 76.1,13.28 76.1,11.84 v1(75.82,11.56)
  BOTTOM w0.142: J9.15 66.5,6.3 68.2,8 72.26,8 v1(75.82,11.56) R249.2 ; v1(67.93,18.73) 67.93,18.96 66.69,20.2 63.97,20.2 63.29,20.88 62.2,21.97 59.05,21.97 58.7,21.62 58.06,21.62 57.41,22.27 57.41,25.75 56.66,26.51 56.66,33.12 57.38,33.84 v1(57.38,36.57)
LCD_DATA13: length 69.7
  TOP w0.142: v1(54.51,10.97) 54.51,11.69 54.39,11.8 54.39,12.47 55.51,13.59 55.51,32.43 57.4,34.32 57.4,35.79 U6.B12 ; R219.2 v1(76.58,13.08)
  L3_SIG1 w0.142: v1(76.58,13.08) 76.58,11.56 71.97,6.95 58.54,6.95 54.84,10.65 54.83,10.65 v1(54.51,10.97)
  BOTTOM w0.142: R219.2 v1(76.58,13.08) 76.58,11.56 72.64,7.62 68.71,7.62 67,5.91 J9.14
LCD_DATA14: length 68
  TOP w0.142: v1(55.02,12.02) 55.02,12.61 55.86,13.45 55.86,32.29 57.8,34.23 U6.A12 ; R218.2 v1(77.34,11.56)
  L3_SIG1 w0.142: v1(77.34,11.56) 72.39,6.6 58.2,6.6 54.03,10.77 54.03,11.48 54.57,12.02 v1(55.02,12.02)
  BOTTOM w0.142: J9.13 67.5,5.85 68.88,7.24 73.03,7.24 v1(77.34,11.56) R251.2
LCD_DATA15: length 59.8
  TOP w0.142: R217.2 v1(78.1,13.08) ; U6.D13 v1(56.58,37.37)
  L3_SIG1 w0.142: v1(54.99,27.94) 58.04,27.94 58.93,27.05 61.51,27.05 63.37,25.19 63.37,21.48 64.04,20.81 65.89,20.81 67.02,19.68 74.04,19.68 78.1,15.62 v1(78.1,13.08)
  BOTTOM w0.142: J9.12 68,5.86 69,6.86 73.32,6.86 77.98,11.52 77.98,11.81 78.1,11.94 v1(78.1,13.08) R217.2 ; v1(56.58,37.37) 56.58,37.22 56.19,36.83 56.19,34.05 55.97,33.83 55.97,28.92 v1(54.99,27.94)
LCD_DATA16: length 23.2
  TOP w0.142: U6.C13 v1(56.58,36.57) ; v1(48.74,30.81) 48.74,30.25 47.91,29.43 47.56,29.43 45.08,26.94 45.08,24.89 45.22,24.75 R253.2 R216.2
  L3_SIG1 w0.142: v1(48.74,30.81) 48.74,30.35 49.25,29.84 52.83,29.84 56.58,33.6 v1(56.58,36.57)
LCD_DATA17: length 16.1
  TOP w0.142: U6.B13 56.64,35.83 56.64,34.8 54.64,32.79 54.64,29.87 51.94,27.18 51.44,27.18 50.68,26.42 50.68,24.89 50.54,24.75 R254.2 R215.2
LCD_DATA18: length 14.7
  TOP w0.142: U6.A13 57,34.67 54.98,32.65 54.98,29.73 52.43,27.18 52.43,25.25 51.92,24.75 R255.2 R214.2
LCD_DATA19: length 24.6
  TOP w0.142: v1(48.25,31.9) 47.34,30.99 47.34,30.46 43.93,27.06 43.93,24.9 44.09,24.75 R256.2 R213.2 ; U6.D14 v1(55.78,37.37)
  L3_SIG1 w0.142: v1(55.78,37.37) 56.18,36.97 56.18,33.7 53.47,30.99 49.78,30.99 48.87,31.9 v1(48.25,31.9)
LCD_DATA20: length 24.9
  TOP w0.142: v1(48.9,32.89) 48.58,32.57 48.19,32.57 46.9,31.28 46.9,30.51 42.55,26.16 42.55,25.02 42.82,24.75 R257.2 R212.2 ; U6.C14 v1(55.78,36.57)
  L3_SIG1 w0.142: v1(55.78,36.57) 55.78,33.79 53.33,31.33 51.22,31.33 49.66,32.89 v1(48.9,32.89)
LCD_DATA21: length 17.9
  TOP w0.142: U6.B14 55.85,35.83 55.85,35.27 53.94,33.37 53.94,30.2 51.69,27.94 49.4,27.94 48.51,27.04 48.51,24.88 48.37,24.75 R258.2 R211.2
LCD_DATA22: length 16.2
  TOP w0.142: R210.2 R259.2 49.51,24.75 49.65,24.88 49.65,27.04 50.13,27.52 51.76,27.52 54.29,30.05 54.29,33.1 56.2,35.01 U6.A14
LCD_DATA23: length 17.9
  TOP w0.142: R209.2 R260.2 47.23,24.75 47.36,24.88 47.36,28.16 47.27,28.25 47.27,28.65 47.71,29.08 49.03,29.08 51.86,31.91 52.27,31.91 52.55,32.19 52.55,32.86 52.58,32.89 52.58,34.92 53.39,35.73 54.15,35.73 U6.B16
LCD_DATA/COMND: length 38
  TOP w0.142: v1(58.48,11.34) 58.14,11.68 58.14,12.41 59.83,14.1 59.83,20.71 58.74,21.8 58.74,22.83 57.64,23.93 57.64,30.33 59.85,32.54 59.85,37.43 U6.D9
  L4_SIG2 w0.142: v1(58.7,3.94) 58.7,4.39 58.42,4.67 58.42,10.83 58.48,10.89 v1(58.48,11.34)
  BOTTOM w0.142: J9.30 59,4.24 v1(58.7,3.94)
LCD_IM0: length 14.8
  BOTTOM w0.142: R195.2 R197.1 79.65,9.02 76.58,9.02 73.66,6.1 69.24,6.1 69,5.85 J9.10
LCD_PWR_EN: length 48
  TOP w0.142: U6.H14 v1(55.78,40.57) ; D12.1 60.58,7.87 59.34,9.12 52.17,9.12 51.89,9.4 v1(51.44,9.4)
  L3_SIG1 w0.142: v1(55.78,40.57) 56.18,40.17 56.48,40.17 56.48,40.17 56.75,40.17 56.98,39.94 56.98,39.66 56.99,39.66 56.99,39.6 57.22,39.37 57.28,39.37 57.28,39.37 57.55,39.37 57.78,39.14 57.78,33.67 53.3,29.19 53.3,26.01 51.92,24.62 51.92,21.03 50.58,19.69 50.58,14.63 51.18,14.02 51.18,11.84 50.75,11.4 50.75,10.08 v1(51.44,9.4)
LCD_RD_E#: length 33.4
  TOP w0.142: U6.B8 61.35,35.83 61.35,31.85 61.3,31.8 61.3,31.72 59.66,30.08 59.66,30.07 59.02,29.43 59.02,24.55 60.93,22.63 60.93,13.5 60.32,12.89 60.32,10.57 60.01,10.25 v1(60.01,9.73)
  BOTTOM w0.142: J9.28 60,5.85 60.01,5.86 v1(60.01,9.73)
LCD_RESET#: length 43.2
  TOP w0.142: U6.E9 60.6,38.18 v1(60.6,37.36)
  L3_SIG1 w0.142: v1(60.6,37.36) 60.92,37.04 60.92,37.02 61.01,36.92 61.01,29.16 62.09,28.08 62.2,28.08 64.23,26.06 64.23,22.9 64.77,22.35 66.04,22.35 67.73,20.67 74.46,20.67 75.18,19.94 78.23,19.94 78.99,19.18 78.99,15.37 v1(79.88,14.48)
  BOTTOM w0.142: v1(79.88,14.48) 79.46,14.05 R807.2 79.46,13.15 79.48,13.12 R808.1 78.99,11.96 R196.1
LCD_WR_E#: length 36.1
  TOP w0.142: U6.A8 61,32.04 58.67,29.72 58.67,24.4 60.59,22.49 60.59,13.64 59.77,12.82 v1(59.77,12.32)
  L4_SIG2 w0.142: v1(59.62,3.56) 60.53,4.47 60.53,11.25 60.09,11.69 60.09,12 v1(59.77,12.32)
  BOTTOM w0.142: v1(59.62,3.56) 59.62,4.02 59.5,4.13 J9.29
LED_ACT/COL_A: length 8
  TOP w0.203: v1(37.72,13.72) 36.83,12.83 D7.1 34.28,12.18 34.29,12.17 R110.1
  BOTTOM w0.142: U10.21 38.36,15.95 37.72,15.31 v1(37.72,13.72)
LED_ACT/COL_B: length 10.7
  TOP w0.142: v1(35.34,33.01) 35.2,33.15 D8.1 34.41,34.26 R128.1
  BOTTOM w0.142: U10.41 40.72,28.37 36.7,32.38 35.51,32.38 35.34,32.56 v1(35.34,33.01)
LED_LINK_A: length 51.6
  L4_SIG2 w0.142: J3.31 14.34,34.33 26.57,34.33 29.72,31.18 29.72,15.88 34.67,10.92 37.91,10.92 38.73,10.09 v1(38.73,9.64)
  BOTTOM w0.142: v1(38.73,9.64) 38.73,11.43 39.01,11.7 R844.2 40.24,12.57 40.56,12.57 41.22,13.23 U10.19
LED_LINK_B: length 64.1
  L3_SIG1 w0.142: v1(39.12,34.16) 38.66,34.16 38.54,34.29 34.92,34.29 31.88,31.24 11.43,31.24 7.91,27.72 7.91,11.73 11.48,8.16 J3.27
  BOTTOM w0.142: v1(39.12,34.16) 39.5,33.77 39.5,32.92 39.93,32.49 R846.2 40.13,30.35 41.72,28.77 U10.43
LED_SPEED_A: length 38.2
  L4_SIG2 w0.142: v1(36.66,9.65) 35.4,9.65 29.34,15.72 29.34,30.99 27.31,33.02 J3.34
  BOTTOM w0.142: v1(36.66,9.65) 37.34,10.33 37.34,11.56 37.48,11.7 R845.1 39.35,12.95 40.08,12.95 40.72,13.59 U10.20
LED_SPEED_B: length 69.4
  L3_SIG1 w0.142: J3.30 22.56,10.03 16.26,10.03 8.26,18.03 8.26,27.18 11.56,30.48 31.77,30.48 33.33,32.04 33.44,32.04 35.09,33.69 35.52,33.69 v1(35.95,33.26)
  BOTTOM w0.142: v1(35.95,33.26) 36.4,33.26 36.43,33.23 36.45,33.23 37.19,32.49 R847.1 38.99,30.73 41.22,28.51 U10.42
LOCAL_PWR: length 5.8
  TOP w0.142: U14.45 72.99,63.66 73.64,63.01 73.64,60.09 73.79,59.95 R141.2
MII_MODE_A: length 5.2
  BOTTOM w0.142: R783.1 53.59,12.79 52.83,13.55 52.83,14.61 53.09,14.86 53.09,15.8 52.94,15.95 U10.80
MII_MODE_B: length 2
  BOTTOM w0.142: U10.62 53.29,24.95 R784.1
NVCC_DRAM_1V35: length 137.2
  TOP w0.142: v1(41.68,41.64) 41.68,43.96 42.67,44.96 42.67,53.85 43.25,54.43 43.25,55.13 43.47,55.35 U1.41 ; v1(43.31,43.7) 43.31,44.07
  TOP w0.254: U7.G7 v1(83.41,41.6) ; U7.R1 v1(77.81,34.41) ; U7.D2 v1(78.61,44) ; U6.G6 v1(63.01,39.77) ; U7.E9 v1(85.01,43.2) ; U7.A1 v1(77.81,46.4) ; U6.M6 v1(63.01,44.6) ; U7.R9 v1(85.01,34.41) ; U7.H9 v1(85.01,40.8) ; U6.K6 v1(63.01,43) ; U7.N1 v1(77.81,36.01) ; U6.J6 v1(63.01,41.37) ; U7.K2 v1(78.61,38.41) ; U7.C1 v1(78.61,44.8) ; U7.F1 v1(77.81,42.4) ; U7.C9 v1(85.01,44.8) ; U7.N9 v1(85.01,36.01) ; U7.D9 v1(85.01,44) ; U7.K8 v1(84.21,38.41) ; U6.L6 v1(63.01,43.8) ; U7.H2 v1(78.61,40.8) ; U7.B2 v1(78.61,45.6) ; U6.H6 v1(63.01,40.57) ; U7.A8 v1(84.21,46.4)
  L4_SIG2 w0.142: 78.23,34.04 78.18,34.04 v1(77.81,34.41) ; v1(41.68,41.64) 41.36,41.32 41.36,40.21 43,38.57 51.56,38.57 52.36,39.37 67.44,39.37 71.65,35.16 77.05,35.16 v1(77.81,34.41) ; 78.21,34.86 78.21,34.86 78.23,34.83 v1(77.81,34.41)
  L4_SIG2 w0.508: v1(68.87,52.83) 68.87,52.19 68.85,52.17 68.85,50.15 71.25,47.75 v1(71.25,46.39)
  BOTTOM w0.142: v1(44.06,44.35) 44.06,44.95 45.3,46.19 45.3,47.91 44.2,49.02 42.93,49.02 42.42,48.51 41.42,48.51 40.89,49.05 35.92,49.05 35.65,49.31 35.65,50.05 33.54,52.16 29.83,52.16 28.99,51.32 28.99,49.82 27.56,48.39 27.56,46.23 28.14,45.65 U22.14
  BOTTOM w0.381: C67.1 C68.1 ; v1(63.01,43.8) C70.1 v1(63.01,44.6) ; C82.1 77.26,42.95 v1(77.81,42.4) ; C85.1 85.15,34.26 v1(85.01,34.41) ; C75.1 84.31,38.51 v1(84.21,38.41) ; v1(63.01,40.57) v1(63.01,41.37) 62.97,41.41 C66.1 62.97,42.96 v1(63.01,43) ; C80.1 85.08,43.28 v1(85.01,43.2) ; C83.1 77.5,46.71 v1(77.81,46.4) ; v1(77.81,36.01) 77,36.01 C81.1 ; C79.1 84.98,44.83 v1(85.01,44.8) ; C86.1 78.63,44.83 v1(78.61,44.8) ; v1(84.21,46.4) 84.35,46.55 C78.1 ; R66.2 65.91,52.47 C87.1 ; v1(85.01,44) 85.22,44.22 C84.1 ; C77.1 85.02,40.79 v1(85.01,40.8) ; v1(77.81,34.41) 77.46,34.06 C74.1 ; C76.1 82.83,41.99 83.21,41.6 v1(83.41,41.6) ; C69.1 v1(63.01,39.77)
  BOTTOM w0.508: C71.1 68.53,43.03 71.25,45.75 v1(71.25,46.39) ; C87.1 66.27,53.32 66.68,53.72 68.07,53.72 68.77,53.03 68.77,52.93 v1(68.87,52.83)
  vias: v1(43.3,44.35) v1(44.07,43.7) v1(44.95,44.47) v1(44.96,43.7)
NVCC_DRAM_1V35_SNS: length 32.6
  TOP w0.381: R186.1 44.88,46.9 44.92,46.86 TP45.1
  BOTTOM w0.142: v1(43.81,47.76) 43.32,47.76 43.05,47.5 43.05,46.16 43.49,45.72 44.34,45.72 44.96,46.34 44.96,47.77 44.05,48.68 43.07,48.68 42.56,48.17 41.28,48.17 40.75,48.7 35.77,48.7 35.31,49.17 35.31,49.91 33.4,51.82 29.97,51.82 29.34,51.18 29.34,49.4 27.96,48.02 27.96,46.44 28.1,46.3 U22.15
NVCC_LCD: length 44.2
  TOP w0.254: U6.E13 v1(56.58,38.17) ; R230.1 R228.2 ; R223.1 73.45,14.58 75.01,14.58 R221.1 R219.1 R217.1
  TOP w0.381: R216.1 v1(45.59,21.94) ; R216.1 R209.1 ; R216.1 R213.1 R212.1 ; 67.26,7.7 67.69,8.13 R231.1 ; R218.1 R220.1 R222.1 R224.1 ; R214.1 R215.1 R210.1 R211.1 ; R209.1 v1(46.74,21.94) ; R209.1 R211.1 ; R211.1 v1(47.88,21.94) ; v1(67.93,14.96) 68.13,14.96 68.47,14.62 R229.1 ; R223.1 73.41,15.49
  TOP w0.508: 68.77,9.16 R230.1 69.91,9.16 ; 77.34,9.44 R218.1 77.92,10.01 ; 68.77,10.01 R228.2 69.91,10.01 ; 72.07,10.01 R224.1 72.64,9.44 ; 67.12,8.49 R231.1 68.26,8.49
  BOTTOM w0.142: 53.79,37.66 53.49,37.36 ; 53.79,37.66 53.91,37.66 54.02,37.77 56.04,37.77 56.44,38.17 v1(56.58,38.17) 56.19,38.57 54.02,38.57 53.79,38.34 53.79,37.66
  BOTTOM w0.254: R70.2 52.02,36.09 52.92,36.99 53.16,37.23 C89.1 53.47,37.36 53.49,37.36
  BOTTOM w0.381: R225.2 R226.2 R227.2 R232.2 81.62,15.6 81.91,15.3 v1(81.91,14.73)
  vias: v1(58.53,19.41) v1(58.8,18.75) v1(68.21,15.67)
NVCC_PLL: length 10.9
  TOP w0.203: U6.P13 v1(56.58,46.2)
  BOTTOM w0.142: C60.1 60.31,48.51 61.6,48.51 62.48,49.4 63.44,49.4 63.82,49.02 TP53.1 ; v1(56.58,46.2) 56.98,46.6 57.55,46.6 57.79,46.83 57.79,47.16 58.02,47.4 58.35,47.4 58.85,47.9
  BOTTOM w0.254: C59.1 59.48,48.67 59.69,48.46 C60.1 58.85,47.9
ON_LS4: length 3.8
  TOP w0.203: U5.C2 v1(31.5,84.32)
  BOTTOM w0.203: R36.2 R806.1 30.77,85.6 31.15,85.21 31.15,84.67 v1(31.5,84.32)
ON_LS5: length 2.6
  TOP w0.142: R31.1 R805.1 30.37,38.88 30.09,39.16 U3.C2
OTG_DM: length 13.6
  TOP w0.127: FL6.2 2.65,31.9 2.91,31.64 2.91,31.14 3.19,30.86 3.9,30.86 4.27,31.23 4.45,31.23 4.58,31.1 4.58,30.91 4.46,30.79 U17.10 U17.1 4.46,28.91 4.54,28.81 4.54,27.97 6.48,26.04 6.48,25.88 6.36,25.76 6.36,25.61 6.47,25.49 6.63,25.49 6.75,25.61 6.9,25.61 7.11,25.4 7.11,24.13 6.98,24 6.6,24 6.46,24.14 J7.2
OTG_DP: length 13.6
  TOP w0.127: FL6.3 3.45,31.9 3.18,31.62 3.18,31.25 3.3,31.13 3.79,31.13 4.16,31.5 4.56,31.5 4.84,31.21 4.84,30.91 4.96,30.79 U17.9 U17.2 4.94,28.91 4.82,28.8 4.81,28.61 4.81,28.08 7.38,25.51 7.38,24.02 7.1,23.74 6.59,23.74 6.35,23.5 J7.3
OTG_PWR: length 107.6
  TOP w0.254: U17.5 U17.6 6.46,30.47 6.98,31 v1(6.98,31.37)
  TOP w0.381: J7.1 v1(5.6,25.65)
  L3_SIG1 w0.508: v1(5.6,25.65) 6.05,26.1 6.05,27.89 6.98,28.83 v1(6.98,31.37)
  L4_SIG2 w0.508: v1(6.98,31.37) 7.75,32.13 7.75,35.03 1.52,41.25 1.52,47.37 3.68,49.53 3.68,69.72 12.57,78.61 22.86,78.61 25.4,76.07 27.69,76.07 31.98,71.78 43.96,71.78 47.54,68.2 v1(49.53,68.2)
  BOTTOM w0.381: C606.2 6.1,25.16 v1(5.6,25.65)
  BOTTOM w0.508: FB3.2 50.29,67.94 50.04,68.2 v1(49.53,68.2)
OVRPRTC: length 3.8
  TOP w0.142: Q3.1 14.84,75.07 14.88,75.04 R9.2 R8.1
OVRPRTC_LED: length 2
  TOP w0.381: D4.1 Q3.3
OVRPRTC_LED_PWR: length 8.7
  TOP w0.381: D4.2 9.18,79.41 10.52,80.75 15.35,80.75 15.37,80.77 R6.2
PB_RESET: length 2.8
  TOP w0.142: SW8.2 97.68,83.36 97.34,83.7 D27.1
PFBIN: length 16.5
  TOP w0.381: 42.8,21.32 C127.1 C126.1 40.37,21.32 v1(40,20.95) 40.02,20.94
  BOTTOM w0.203: U10.7 47.22,13.31 46.97,13.06 C577.1 ; U10.31 v1(40,20.95)
  BOTTOM w0.254: C574.1 46.84,28.79 47.22,28.42 U10.54 ; U10.34 37.84,22.45 37.76,22.37 C576.1 ; U10.28 37.84,19.45 37.76,19.54 C575.1
  BOTTOM w0.381: C574.1 46.84,29.95 46.89,29.99 46.89,31.47 v1(46.48,31.87) ; C576.1 v1(36.32,22.37) ; v1(47.05,11.82) 46.97,11.89 C577.1 ; C575.1 v1(36.3,19.54)
PFO#: length 45.1
  TOP w0.142: U6.R9 60.58,46.96 60.58,48.89 59.94,49.53 59.94,51.82 62.74,54.61 62.74,58.28 60.77,60.25 60.77,62.93 59.18,64.52 59.18,70.74 59.54,71.09 59.54,73.18 59.1,73.62 53.43,73.62 52.32,72.52 52.32,70.57 53.34,69.55 53.34,67.82 52.81,67.29 R27.2 R860.1
PGOOD: length 5.1
  TOP w0.142: U1.8 47.84,59.53 48.47,60.16 51.12,60.16 R769.2
PGOOD_BU: length 4.1
  TOP w0.142: U1.19 43.87,62.99 43.76,63.11 v1(43.76,63.51)
  BOTTOM w0.142: v1(43.76,63.51) 43.76,64.95 R768.2
PHY_MDC: length 43.1
  TOP w0.142: TP5.1 49.52,20.71 49.52,21.09 v1(49.11,21.51) ; v1(41.15,36.96) 41.6,36.96 41.76,37.12 42.69,37.12 43.61,38.04 46.16,38.04 51,42.87 53.04,42.87 53.2,43.03 54.25,43.03 U6.L16
  L4_SIG2 w0.142: v1(41.15,36.96) 40.1,35.91 40.1,35.87 40.01,35.77 40.01,27.81 44.45,23.37 48.26,23.37 48.79,22.84 48.79,21.83 v1(49.11,21.51)
  BOTTOM w0.142: v1(49.11,21.51) 49.64,22.04 50.48,22.04 50.9,22.45 U10.67
PHY_MDIO: length 45.8
  TOP w0.142: v1(48.26,21.21) 47.62,20.57 TP6.1 46.25,20.57 R113.1 ; v1(42.16,36.48) 42.62,36.48 43.81,37.68 46.29,37.68 49.38,40.77 49.4,40.77 51.16,42.52 53.36,42.52 53.42,42.58 U6.K17
  L4_SIG2 w0.142: v1(42.16,36.48) 41.23,36.48 40.35,35.61 40.35,28.1 44.74,23.71 48.59,23.71 49.58,22.72 49.58,21.31 49.3,21.03 48.91,21.03 48.73,21.21 v1(48.26,21.21)
  BOTTOM w0.142: U10.66 49.87,22.95 48.32,21.4 48.32,21.27 v1(48.26,21.21)
PHYA_CRSDV: length 45.3
  TOP w0.142: U6.E16 v1(54.18,38.17)
  L3_SIG1 w0.142: v1(46.74,10.03) 46.74,11.16 46.51,11.39 46.51,15.66 47.53,16.68 47.53,21.61 47.21,21.93 47.21,22.14 46.93,22.42 46.72,22.42 46.23,22.91 46.23,27.31 45.25,28.29 45.25,33.68 47.21,35.65 50.62,35.65 51.56,36.58 52.74,36.58 54.05,37.89 54.05,38.04 v1(54.18,38.17)
  BOTTOM w0.142: v1(46.74,10.03) 48.13,8.64 51.94,8.64 52.45,9.14 R119.1
PHYA_MDI_1_N: length 24.1
  BOTTOM w0.102: J3.13 22.83,19.47 22.83,20.06 23.22,20.45 24.39,20.45 24.5,20.35 24.5,19.79 24.6,19.68 24.8,19.68 24.9,19.79 24.9,20.35 25,20.45 25.21,20.45 25.31,20.35 25.31,19.79 25.41,19.68 25.61,19.68 25.72,19.79 25.72,20.35 25.82,20.45 27.81,20.45 29.21,19.05 29.21,17.25 29.57,16.89 29.83,16.89 29.96,16.76 U11.9 U11.2 31.56,16.78 31.68,16.91 31.82,16.92 31.91,16.92 32.69,17.7 32.69,17.85 32.93,18.1 33.36,18.1 R791.2 34.21,18.1 35.73,18.1 36.21,18.57 37.92,18.57 38.05,18.45 U10.26
PHYA_MDI_1_P: length 24.2
  BOTTOM w0.102: J3.6 22.51,17.21 22.5,17.22 22.5,20.08 23.11,20.7 27.92,20.7 29.46,19.16 29.46,17.36 29.68,17.14 29.83,17.14 29.94,17.26 U11.10 U11.1 31.54,17.28 31.66,17.16 31.81,17.17 32.44,17.8 32.44,17.96 32.83,18.35 33.36,18.35 R790.1 34.21,18.35 35.62,18.35 36.1,18.83 37.92,18.83 38.05,18.95 U10.27
PHYA_MDI_2_N: length 25.4
  BOTTOM w0.102: J3.5 20.5,15.29 21.72,14.07 22.32,14.07 22.43,13.97 22.43,13.41 22.53,13.31 22.73,13.31 22.83,13.41 22.83,13.97 22.93,14.07 23.14,14.07 23.24,13.97 23.24,13.41 23.34,13.31 23.54,13.31 23.64,13.41 23.64,13.97 23.75,14.07 28.04,14.07 29.35,15.38 29.56,15.38 29.68,15.26 U11.6 U11.5 31.54,15.26 31.66,15.38 31.8,15.38 32,15.18 32,15.01 32.85,14.16 33.36,14.16 R793.2 34.21,14.16 35.09,14.16 35.81,14.88 35.81,15.11 37.78,17.07 37.92,17.07 38.04,16.95 U10.23
PHYA_MDI_2_P: length 25.5
  BOTTOM w0.102: J3.11 21.5,16.77 21.5,14.64 21.82,14.33 27.94,14.33 29.24,15.63 29.56,15.63 29.68,15.76 U11.7 U11.4 31.54,15.76 31.66,15.63 31.91,15.63 32.26,15.28 32.26,15.11 32.96,14.41 33.36,14.41 R792.1 34.21,14.41 34.99,14.41 35.55,14.98 35.55,15.21 37.67,17.33 37.92,17.33 38.05,17.45 U10.24
PHYA_RXD0: length 40.2
  TOP w0.142: R112.2 47.14,18.29 v1(44.96,18.29) ; U6.F16 v1(54.18,38.97)
  L3_SIG1 w0.142: v1(44.96,18.29) 44.96,20.74 42.86,22.84 42.86,23.2 41.18,24.88 41.18,27.24 41.06,27.36 40.8,27.36 40.68,27.49 40.68,27.66 40.8,27.79 41.06,27.79 41.18,27.91 41.18,28.09 41.06,28.22 40.8,28.22 40.68,28.34 40.68,28.52 40.8,28.64 41.06,28.64 41.18,28.77 41.18,28.95 41.06,29.07 40.8,29.07 40.68,29.2 40.68,29.37 40.8,29.5 41.06,29.5 41.18,29.62 41.18,29.8 41.06,29.92 40.8,29.92 40.68,30.05 40.68,30.23 40.8,30.35 41.06,30.35 41.18,30.48 41.18,30.65 41.06,30.78 40.8,30.78 40.68,30.9 40.68,31.08 40.8,31.2 41.06,31.2 41.18,31.33 41.18,31.77 42.16,32.75 42.45,32.75 43.76,34.06 43.76,34.88 45.57,36.68 45.57,37.3 46.78,38.52 48.54,38.52 48.67,38.39 48.67,37.98 48.79,37.86 48.97,37.86 49.09,37.98 49.09,38.39 49.22,38.52 53.01,38.52 53.06,38.57 53.57,38.57 53.96,38.97 v1(54.18,38.97)
PHYA_RXD1: length 40.6
  TOP w0.142: R117.2 v1(45.74,17.67) ; U6.E17 v1(53.38,38.17)
  L3_SIG1 w0.142: v1(45.74,17.67) 45.74,18.39 46.07,18.73 46.07,20.12 43.21,22.98 43.21,23.34 42.65,23.9 42.65,24.08 42.96,24.39 42.96,24.57 42.83,24.69 42.66,24.69 42.34,24.38 42.17,24.38 41.82,24.73 41.82,25.64 41.94,25.76 42.58,25.76 42.71,25.89 42.71,26.06 42.58,26.19 41.94,26.19 41.82,26.31 41.82,26.49 41.94,26.61 42.58,26.61 42.71,26.74 42.71,26.92 42.58,27.04 41.94,27.04 41.82,27.17 41.82,27.34 41.94,27.47 42.58,27.47 42.71,27.59 42.71,27.77 42.58,27.89 41.94,27.89 41.82,28.02 41.82,28.2 41.94,28.32 42.58,28.32 42.71,28.45 42.71,28.62 42.58,28.75 41.94,28.75 41.82,28.87 41.82,29.05 41.94,29.17 42.58,29.17 42.71,29.3 42.71,29.48 42.58,29.6 41.94,29.6 41.82,29.73 41.82,31.68 42.54,32.4 42.6,32.4 44.11,33.91 44.11,34.74 45.95,36.58 46.27,36.58 47.2,37.51 49.86,37.51 50.52,38.17 v1(53.38,38.17)
PHYA_RXER: length 47
  TOP w0.142: U6.D15 v1(54.98,37.37)
  L3_SIG1 w0.142: v1(54.98,37.37) 54.58,36.97 53.86,36.97 53.01,36.12 51.75,36.12 50.89,35.27 47.32,35.27 45.59,33.54 45.59,28.58 47.37,26.8 47.37,25.22 47.25,25.09 46.86,25.09 46.73,24.97 46.73,24.79 46.86,24.67 47.92,24.67 48.05,24.54 48.05,24.36 47.92,24.24 46.86,24.24 46.73,24.11 46.73,23.94 46.86,23.81 47.86,23.81 47.99,23.69 47.99,23.51 47.86,23.39 46.86,23.39 46.73,23.26 46.73,23.08 46.86,22.96 47.25,22.96 47.69,22.51 48.78,22.51 49.58,21.7 49.58,21.31 49.3,21.03 48.76,21.03 48.58,20.86 48.58,20.02 48.74,19.87 48.74,17.37 47.37,16 47.37,15.45 47.2,15.28 47.2,13.35 48.23,12.32 48.23,11.23 v1(47.56,10.56)
  BOTTOM w0.142: v1(47.56,10.56) 48.01,10.56 48.27,10.31 R114.1 R118.2
PHYA_TX_EN: length 2.5
  BOTTOM w0.142: U10.13 44.22,12.47 43.94,12.19 R80.1
PHYA_TXD0: length 4.5
  BOTTOM w0.142: U10.14 43.72,12.46 43.43,12.17 43.43,10.17 43.43,10.16 R78.1
PHYA_TXD1: length 2.5
  BOTTOM w0.142: U10.15 43.22,12.86 42.8,12.45 R79.1
PHYB_CRSDV: length 11.5
  TOP w0.142: v1(52.07,32.38) 52.07,35.05 53.2,36.18 U6.B17
  BOTTOM w0.142: R126.1 53.34,30.58 53.46,30.71 54.91,30.71 55.04,30.83 55.04,31.01 54.91,31.13 53.46,31.13 53.34,31.26 53.34,31.87 52.83,32.38 v1(52.07,32.38)
PHYB_MDI_1_N: length 31.2
  BOTTOM w0.102: U10.36 38.05,23.45 37.92,23.33 36.62,23.33 34.73,25.21 33.95,25.21 R795.2 33.1,25.21 32.58,25.21 32.08,25.71 32.08,26.6 31.36,27.32 31.02,27.32 30.9,27.44 U12.9 U12.2 29.02,27.41 28.9,27.29 28.76,27.28 28.19,27.28 26.18,25.27 16.22,25.27 15.48,26.02 15.48,27.18 J3.21
PHYB_MDI_1_P: length 31.1
  BOTTOM w0.102: U10.35 38.04,22.95 37.92,23.07 36.51,23.07 34.63,24.96 33.95,24.96 R794.1 33.1,24.96 32.47,24.96 31.82,25.6 31.82,26.49 31.25,27.06 31.02,27.06 30.9,26.94 U12.10 U12.1 29.04,26.91 28.91,27.03 28.77,27.02 28.29,27.02 26.29,25.02 17.97,25.02 17.87,24.92 17.87,24.36 17.77,24.26 17.56,24.26 17.46,24.36 17.46,24.92 17.36,25.02 17.16,25.02 17.06,24.92 17.06,24.36 16.95,24.26 16.75,24.26 16.65,24.36 16.65,24.92 16.55,25.02 16.12,25.02 J3.15
PHYB_MDI_2_N: length 30.8
  BOTTOM w0.102: J3.16 16.48,27.62 16.47,27.63 16.47,30.44 17.4,31.37 23.83,31.37 26.38,28.82 28.92,28.82 29.04,28.94 U12.5 U12.6 30.9,28.94 31.02,28.82 32.01,28.82 32.09,28.89 33.1,28.89 R797.2 33.95,28.89 34.86,28.89 35.94,27.81 35.94,26.16 37.28,24.83 37.92,24.83 38.05,24.95 U10.39
PHYB_MDI_2_P: length 30.7
  BOTTOM w0.102: U10.38 38.05,24.45 37.92,24.57 37.17,24.57 35.69,26.06 35.69,27.71 34.76,28.64 33.95,28.64 R796.1 33.1,28.64 32.19,28.64 32.12,28.56 31.02,28.56 30.9,28.44 U12.7 U12.4 29.04,28.44 28.92,28.56 26.28,28.56 23.72,31.12 19.46,31.12 19.37,31.03 19.37,30.73 19.28,30.65 19.16,30.65 19.07,30.73 19.07,31.03 18.98,31.12 18.85,31.12 18.76,31.03 18.76,30.73 18.67,30.65 18.55,30.65 18.46,30.73 18.46,31.03 18.37,31.12 18.24,31.12 18.15,31.03 18.15,30.73 18.06,30.65 17.94,30.65 17.85,30.73 17.85,31.03 17.76,31.12 17.5,31.12 16.72,30.33 16.72,29.31 16.82,29.21 J3.23
